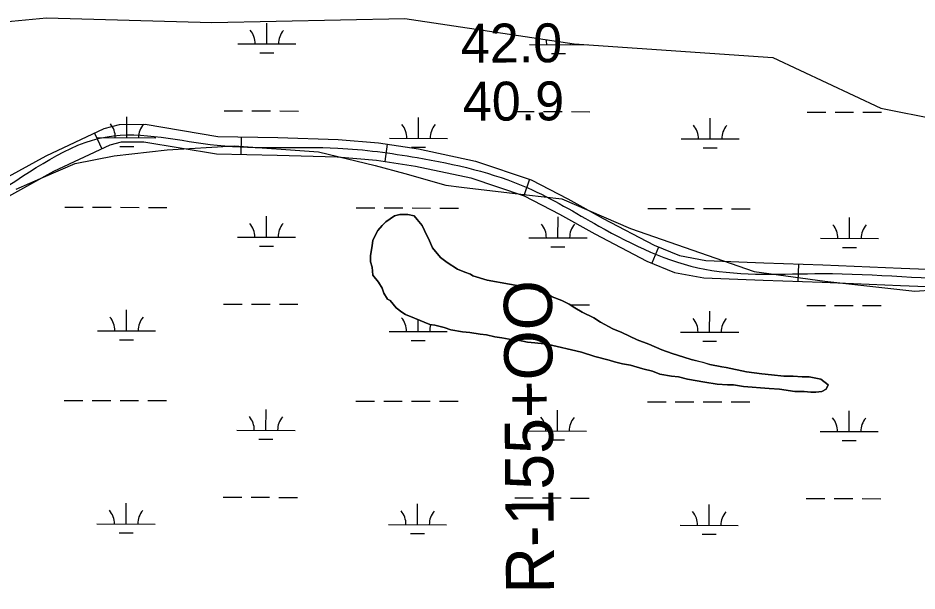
# Model space of a CAD drawing. Extents: x 3180038 to 3217926, y 922069 to 947485.
# Drawn here: x 3184913 to 3186460, y 931017 to 932004 of the extents above; entities that cross this region are included whole.
import ezdxf

# ---------------------------------------------------------------- set-up
doc = ezdxf.new("R2010")
doc.units = 0
for name, color, linetype in [('V-RIVR-RANG', 7, 'Continuous'), ('V-RIVR-RANG-IDEN', 7, 'Continuous'), ('V-ROAD-CNTR', 7, 'Continuous'), ('V-SITE-VEGE', 7, 'Continuous'), ('V-TOPO-SHOR', 7, 'Continuous'), ('V-WETL-SWMP', 7, 'Continuous')]:
    doc.layers.add(name, color=color, linetype=linetype)

msp = doc.modelspace()

# ---------------------------------------------------------------- linework, layer by layer
at = {"layer": 'V-ROAD-CNTR'}
for p, q in [((3185044.5, 931805.8), (3185057.3, 931778.7)), ((3185297.1, 931799.1), (3185296.5, 931769.1)), ((3185548.5, 931786.4), (3185544.1, 931756.8)), ((3185793.3, 931726.3), (3185783.7, 931697.9)), ((3186015.3, 931609.5), (3186003.9, 931581.8)), ((3186256.2, 931580.3), (3186255.1, 931550.3))]:
    msp.add_line(p, q, dxfattribs=at)
for points in [[(3184866.8, 931714.7), (3184961.2, 931766.7), (3185061.1, 931813.6), (3185087.4, 931820.4), (3185131.6, 931821), (3185257.2, 931799.9), (3185360, 931797.9), (3185464.3, 931794.9), (3185533.6, 931788.7), (3185602.6, 931778.4), (3185700.5, 931757.6), (3185796.2, 931725.3), (3185859.2, 931692.5), (3185920.1, 931658.7), (3186008, 931612.5), (3186051.6, 931594.7), (3186096.7, 931586.3), (3186196.9, 931582.4), (3186298.2, 931578.8), (3186433.1, 931573.4), (3186567.7, 931568)], [(3184881.1, 931688.3), (3184974.8, 931740), (3185071.3, 931785.3), (3185091.3, 931790.4), (3185129.3, 931790.9), (3185254.4, 931770), (3185359.3, 931767.9), (3185462.5, 931764.9), (3185530, 931758.9), (3185597.3, 931748.9), (3185692.6, 931728.7), (3185784.4, 931697.6), (3185845, 931666.1), (3185905.9, 931632.3), (3185995.4, 931585.3), (3186043.1, 931565.8), (3186093.3, 931556.4), (3186195.8, 931552.4), (3186297.1, 931548.9), (3186431.9, 931543.4), (3186567.2, 931538)]]:
    msp.add_lwpolyline(points, dxfattribs=at)
msp.add_spline([(3184272.5, 931571.5), (3184273.3, 931572), (3184388.9, 931608.9), (3184482.3, 931629.3), (3184594.3, 931629), (3184801.1, 931663.1), (3184874, 931701.5), (3185066.2, 931799.5), (3185255.8, 931784.9), (3185463.4, 931779.9), (3185599.9, 931763.6), (3185790.3, 931711.5), (3185913, 931645.5), (3186095, 931571.4), (3186297.6, 931563.8), (3186567.5, 931553), (3186727.4, 931556.9), (3186879, 931529.3), (3186914.3, 931400.2), (3186887.7, 931205.9), (3186857.5, 930948.7), (3186884.4, 930867.9), (3186934.5, 930827.1), (3186969.1, 930750.7), (3186952, 930670.5)], degree=3, dxfattribs=at)
at = {"layer": 'V-SITE-VEGE'}
for p, q in [((3185546.1, 931653.1), (3185561.2, 931663.1)), ((3185561.2, 931663.1), (3185570, 931665.6)), ((3185570, 931665.6), (3185583.8, 931665.7)), ((3185583.8, 931665.7), (3185595.1, 931663.1)), ((3185595.1, 931663.1), (3185600.1, 931656.9)), ((3185539.8, 931646.8), (3185546.1, 931653.1)), ((3185600.1, 931656.9), (3185608.9, 931646.8)), ((3185523.5, 931621.6), (3185532.3, 931638)), ((3185532.3, 931638), (3185539.8, 931646.8)), ((3185608.9, 931646.8), (3185612.7, 931638)), ((3185612.7, 931638), (3185621.5, 931620.4)), ((3185522.3, 931611.6), (3185523.5, 931621.6)), ((3185621.5, 931620.4), (3185626.5, 931607.9)), ((3185519.8, 931595.2), (3185522.3, 931611.6)), ((3185626.5, 931607.9), (3185640.4, 931591.6)), ((3185519.8, 931583.9), (3185519.8, 931595.2)), ((3185640.4, 931591.6), (3185651.7, 931582.8)), ((3185522.3, 931575.1), (3185519.8, 931583.9)), ((3185523.5, 931561.3), (3185522.3, 931575.1)), ((3185651.7, 931582.8), (3185669.3, 931571.5)), ((3185669.3, 931571.5), (3185681.9, 931566.5)), ((3185533.6, 931548.8), (3185523.5, 931561.3)), ((3185681.9, 931566.5), (3185691.9, 931562.7)), ((3185691.9, 931562.7), (3185695.7, 931560.2)), ((3185695.7, 931560.2), (3185720.8, 931552.7)), ((3185539.9, 931538.7), (3185533.6, 931548.8)), ((3185542.4, 931529.9), (3185539.9, 931538.7)), ((3185720.8, 931552.7), (3185797.5, 931538.9)), ((3185797.5, 931538.9), (3185806.3, 931536.4)), ((3185548.7, 931519.9), (3185542.4, 931529.9)), ((3185806.3, 931536.4), (3185812.6, 931532.6)), ((3185812.6, 931532.6), (3185822.6, 931530.1)), ((3185822.6, 931530.1), (3185832.7, 931523.8)), ((3185832.7, 931523.8), (3185849, 931517.6)), ((3185553.7, 931517.4), (3185548.7, 931519.9)), ((3185563.8, 931504.8), (3185553.7, 931517.4)), ((3185849, 931517.6), (3185861.6, 931511.3)), ((3185861.6, 931511.3), (3185871.6, 931505)), ((3185573.9, 931497.3), (3185563.8, 931504.8)), ((3185580.1, 931493.5), (3185573.9, 931497.3)), ((3185595.2, 931487.2), (3185580.1, 931493.5)), ((3185871.6, 931505), (3185884.2, 931497.5)), ((3185884.2, 931497.5), (3185904.3, 931487.5)), ((3185621.6, 931476), (3185595.2, 931487.2)), ((3185904.3, 931487.5), (3185915.6, 931479.9)), ((3185915.6, 931479.9), (3185937, 931468.6)), ((3185630.4, 931474.7), (3185621.6, 931476)), ((3185646.7, 931470.9), (3185630.4, 931474.7)), ((3185658.1, 931467.2), (3185646.7, 931470.9)), ((3185678.2, 931463.4), (3185658.1, 931467.2)), ((3185690.7, 931462.2), (3185678.2, 931463.4)), ((3185708.3, 931459.7), (3185690.7, 931462.2)), ((3185937, 931468.6), (3185952.1, 931462.4)), ((3185952.1, 931462.4), (3185978.5, 931449.8)), ((3185719.6, 931458.4), (3185708.3, 931459.7)), ((3185733.5, 931454.7), (3185719.6, 931458.4)), ((3185746, 931453.4), (3185733.5, 931454.7)), ((3185758.6, 931450.9), (3185746, 931453.4)), ((3185771.2, 931449.7), (3185758.6, 931450.9)), ((3185790, 931445.9), (3185771.2, 931449.7)), ((3185802.6, 931444.7), (3185790, 931445.9)), ((3185978.5, 931449.8), (3185998.6, 931442.3)), ((3185823.9, 931442.2), (3185802.6, 931444.7)), ((3185883, 931428.4), (3185823.9, 931442.2)), ((3185998.6, 931442.3), (3186021.2, 931432.3)), ((3186021.2, 931432.3), (3186038.8, 931426)), ((3185905.6, 931420.9), (3185883, 931428.4)), ((3185930.7, 931414.6), (3185905.6, 931420.9)), ((3186038.8, 931426), (3186058.9, 931419.7)), ((3186058.9, 931419.7), (3186071.5, 931416)), ((3186071.5, 931416), (3186091.6, 931411)), ((3185939.5, 931412.1), (3185930.7, 931414.6)), ((3185953.4, 931408.3), (3185939.5, 931412.1)), ((3185967.2, 931405.8), (3185953.4, 931408.3)), ((3185988.6, 931399.6), (3185967.2, 931405.8)), ((3186004.9, 931395.8), (3185988.6, 931399.6)), ((3186091.6, 931411), (3186104.1, 931407.2)), ((3186104.1, 931407.2), (3186124.2, 931403.4)), ((3186124.2, 931403.4), (3186131.8, 931402.2)), ((3186131.8, 931402.2), (3186167, 931394.7)), ((3186017.5, 931390.8), (3186004.9, 931395.8)), ((3186037.6, 931387), (3186017.5, 931390.8)), ((3186050.1, 931385.8), (3186037.6, 931387)), ((3186065.2, 931382), (3186050.1, 931385.8)), ((3186167, 931394.7), (3186193.4, 931390.9)), ((3186193.4, 931390.9), (3186209.7, 931389.7)), ((3186209.7, 931389.7), (3186231.1, 931387.2)), ((3186231.1, 931387.2), (3186247.4, 931387.2)), ((3186247.4, 931387.2), (3186262.5, 931385.9)), ((3186262.5, 931385.9), (3186275, 931386)), ((3186275, 931386), (3186295.1, 931382.2)), ((3186095.4, 931377), (3186065.2, 931382)), ((3186116.7, 931373.3), (3186095.4, 931377)), ((3186134.3, 931372), (3186116.7, 931373.3)), ((3186144.4, 931372), (3186134.3, 931372)), ((3186162, 931369.5), (3186144.4, 931372)), ((3186205.9, 931365.8), (3186162, 931369.5)), ((3186295.1, 931382.2), (3186307.7, 931372.2)), ((3186307.7, 931372.2), (3186304, 931364.6)), ((3186223.5, 931364.6), (3186205.9, 931365.8)), ((3186249.9, 931360.8), (3186223.5, 931364.6)), ((3186266.3, 931360.8), (3186249.9, 931360.8)), ((3186277.6, 931359.6), (3186266.3, 931360.8)), ((3186286.4, 931359.6), (3186277.6, 931359.6)), ((3186296.4, 931360.8), (3186286.4, 931359.6)), ((3186304, 931364.6), (3186296.4, 931360.8))]:
    msp.add_line(p, q, dxfattribs=at)
at = {"layer": 'V-TOPO-SHOR'}
msp.add_lwpolyline([(3184909.8, 931709.3), (3184957.1, 931729.6), (3185011.2, 931753.2), (3185078.7, 931766.7), (3185169.9, 931776.9), (3185284.8, 931783.6), (3185430, 931773.5), (3185528, 931749.8), (3185578.7, 931736.3), (3185649.6, 931716.1), (3185676.6, 931712.7), (3185788.1, 931699.2), (3185848.9, 931692.4), (3185967.1, 931641.7), (3186179.9, 931567.4), (3186301.6, 931550.5), (3186456.9, 931533.6), (3186554.9, 931540.4)], dxfattribs=at)
at = {"layer": 'V-WETL-SWMP'}
for p, q in [((3184691, 931979.1), (3184961.8, 932004)), ((3184961.8, 932004), (3185246.5, 931996.2)), ((3185246.5, 931996.2), (3185579, 932003)), ((3185579, 932003), (3185870.2, 931959.6)), ((3185341.3, 931959.3), (3185341.4, 931995.3)), ((3185291.3, 931959.4), (3185391.3, 931959.2)), ((3185793.2, 931958.3), (3185892.8, 931958)), ((3185843.2, 931958.1), (3185843.2, 931963.6)), ((3185870.2, 931959.6), (3186212.2, 931935.9)), ((3185329.2, 931943.9), (3185353.2, 931943.8)), ((3185831.1, 931942.7), (3185855.1, 931942.7)), ((3186212.2, 931935.9), (3186398.1, 931848.9)), ((3186398.1, 931848.9), (3186672.6, 931793.9)), ((3185100.4, 931798), (3185100.5, 931834)), ((3185267.6, 931844), (3185299.6, 931843.9)), ((3185315.6, 931843.9), (3185347.6, 931843.8)), ((3185363.6, 931843.8), (3185395.6, 931843.7)), ((3185602.3, 931796.8), (3185602.4, 931832.8)), ((3185769.5, 931842.9), (3185801.5, 931842.8)), ((3185817.5, 931842.8), (3185849.5, 931842.7)), ((3185865.5, 931842.7), (3185897.5, 931842.6)), ((3186271.4, 931841.7), (3186303.4, 931841.7)), ((3186319.4, 931841.6), (3186351.4, 931841.6)), ((3186367.4, 931841.5), (3186399.4, 931841.5)), ((3186104.3, 931795.7), (3186104.3, 931831.7)), ((3185050.4, 931798.1), (3185150.4, 931797.8)), ((3185552.3, 931796.9), (3185652.3, 931796.7)), ((3186054.3, 931795.8), (3186154.3, 931795.6)), ((3185088.4, 931782.6), (3185112.4, 931782.5)), ((3185590.3, 931781.4), (3185614.3, 931781.4)), ((3186092.2, 931780.3), (3186116.2, 931780.2)), ((3184993.3, 931678.1), (3185025.3, 931678.1)), ((3185041.3, 931678), (3185073.3, 931677.9)), ((3185089.3, 931677.9), (3185121.3, 931677.8)), ((3185137.3, 931677.8), (3185169.3, 931677.7)), ((3185340.5, 931626.6), (3185340.6, 931662.6)), ((3185495.2, 931677), (3185527.2, 931676.9)), ((3185543.2, 931676.9), (3185575.2, 931676.8)), ((3185561.2, 931663.1), (3185546.1, 931653.1)), ((3185570, 931665.6), (3185561.2, 931663.1)), ((3185583.8, 931665.6), (3185570, 931665.6)), ((3185595.1, 931663.1), (3185583.8, 931665.6)), ((3185591.2, 931676.8), (3185623.2, 931676.7)), ((3185600.1, 931656.9), (3185595.1, 931663.1)), ((3185639.2, 931676.7), (3185671.2, 931676.6)), ((3185997.1, 931675.9), (3186029.1, 931675.8)), ((3186045.1, 931675.8), (3186077.1, 931675.7)), ((3186093.1, 931675.6), (3186125.1, 931675.6)), ((3186141.1, 931675.5), (3186173.1, 931675.5)), ((3185546.1, 931653.1), (3185539.8, 931646.8)), ((3185608.9, 931646.8), (3185600.1, 931656.9)), ((3185842.4, 931625.5), (3185842.5, 931661.5)), ((3186344.3, 931624.3), (3186344.4, 931660.3)), ((3185532.3, 931638), (3185523.5, 931621.6)), ((3185539.8, 931646.8), (3185532.3, 931638)), ((3185612.7, 931638), (3185608.9, 931646.8)), ((3185621.5, 931620.4), (3185612.7, 931638)), ((3185290.5, 931626.7), (3185390.5, 931626.5)), ((3185523.5, 931621.6), (3185522.3, 931611.6)), ((3185626.5, 931607.9), (3185621.5, 931620.4)), ((3185792.4, 931625.6), (3185892.4, 931625.4)), ((3186294.3, 931624.5), (3186394.3, 931624.2)), ((3185328.5, 931611.2), (3185352.5, 931611.1)), ((3185522.3, 931611.6), (3185519.8, 931595.2)), ((3185640.4, 931591.6), (3185626.5, 931607.9)), ((3185830.4, 931610.1), (3185854.4, 931610)), ((3186332.3, 931608.9), (3186356.3, 931608.9)), ((3185519.8, 931595.2), (3185519.8, 931583.9)), ((3185651.7, 931582.8), (3185640.4, 931591.6)), ((3185519.8, 931583.9), (3185522.3, 931575.1)), ((3185522.3, 931575.1), (3185523.6, 931561.3)), ((3185669.3, 931571.5), (3185651.7, 931582.8)), ((3185681.9, 931566.5), (3185669.3, 931571.5)), ((3185523.6, 931561.3), (3185533.6, 931548.8)), ((3185691.9, 931562.7), (3185681.9, 931566.5)), ((3185695.7, 931560.2), (3185691.9, 931562.7)), ((3185720.8, 931552.7), (3185695.7, 931560.2)), ((3185533.6, 931548.8), (3185539.9, 931538.7)), ((3185539.9, 931538.7), (3185542.4, 931529.9)), ((3185797.5, 931538.9), (3185720.8, 931552.7)), ((3185806.3, 931536.4), (3185797.5, 931538.9)), ((3185542.4, 931529.9), (3185548.7, 931519.9)), ((3185812.6, 931532.6), (3185806.3, 931536.4)), ((3185822.6, 931530.1), (3185812.6, 931532.6)), ((3185832.7, 931523.8), (3185822.6, 931530.1)), ((3185849, 931517.6), (3185832.7, 931523.8)), ((3185266.9, 931511.3), (3185298.9, 931511.3)), ((3185314.9, 931511.2), (3185346.9, 931511.2)), ((3185362.9, 931511.1), (3185394.9, 931511)), ((3185548.7, 931519.9), (3185553.7, 931517.4)), ((3185553.7, 931517.4), (3185563.8, 931504.8)), ((3185861.6, 931511.3), (3185849, 931517.6)), ((3185871.6, 931505), (3185861.6, 931511.3)), ((3185864.8, 931510), (3185896.8, 931509.9)), ((3186270.7, 931509.1), (3186302.7, 931509)), ((3186318.7, 931509), (3186350.7, 931508.9)), ((3186366.7, 931508.9), (3186398.7, 931508.8)), ((3185099.7, 931465.3), (3185099.8, 931501.3)), ((3185563.8, 931504.8), (3185573.9, 931497.3)), ((3185573.9, 931497.3), (3185580.1, 931493.5)), ((3185580.1, 931493.5), (3185595.2, 931487.2)), ((3185884.2, 931497.5), (3185871.6, 931505)), ((3185904.3, 931487.5), (3185884.2, 931497.5)), ((3186103.5, 931463), (3186103.6, 931499)), ((3185595.2, 931487.2), (3185621.6, 931475.9)), ((3185601.6, 931464.2), (3185601.6, 931484.5)), ((3185915.6, 931479.9), (3185904.3, 931487.5)), ((3185937, 931468.6), (3185915.6, 931479.9)), ((3185049.7, 931465.4), (3185149.7, 931465.2)), ((3185551.6, 931464.3), (3185651.6, 931464)), ((3185621.6, 931475.9), (3185630.4, 931474.7)), ((3185630.4, 931474.7), (3185646.7, 931470.9)), ((3185646.7, 931470.9), (3185658.1, 931467.2)), ((3185658.1, 931467.2), (3185678.2, 931463.4)), ((3185678.2, 931463.4), (3185690.7, 931462.2)), ((3185690.7, 931462.2), (3185708.3, 931459.7)), ((3185952.1, 931462.4), (3185937, 931468.6)), ((3185978.5, 931449.8), (3185952.1, 931462.4)), ((3186053.5, 931463.1), (3186153.5, 931462.9)), ((3185087.7, 931449.9), (3185111.7, 931449.8)), ((3185589.6, 931448.7), (3185613.6, 931448.7)), ((3185708.3, 931459.7), (3185719.6, 931458.4)), ((3185719.6, 931458.4), (3185733.5, 931454.7)), ((3185733.5, 931454.7), (3185746, 931453.4)), ((3185746, 931453.4), (3185758.6, 931450.9)), ((3185758.6, 931450.9), (3185771.2, 931449.7)), ((3185771.2, 931449.7), (3185790, 931445.9)), ((3185790, 931445.9), (3185802.6, 931444.7)), ((3185998.6, 931442.3), (3185978.5, 931449.8)), ((3186091.5, 931447.6), (3186115.5, 931447.6)), ((3185802.6, 931444.7), (3185823.9, 931442.2)), ((3185823.9, 931442.2), (3185883, 931428.4)), ((3186021.2, 931432.3), (3185998.6, 931442.3)), ((3186038.8, 931426), (3186021.2, 931432.3)), ((3185883, 931428.4), (3185905.6, 931420.9)), ((3185905.6, 931420.9), (3185930.7, 931414.6)), ((3186058.9, 931419.7), (3186038.8, 931426)), ((3186071.5, 931416), (3186058.9, 931419.7)), ((3186091.6, 931410.9), (3186071.5, 931416)), ((3185930.7, 931414.6), (3185939.5, 931412.1)), ((3185939.5, 931412.1), (3185953.4, 931408.3)), ((3185953.4, 931408.3), (3185967.2, 931405.8)), ((3185967.2, 931405.8), (3185988.6, 931399.6)), ((3185988.6, 931399.6), (3186004.9, 931395.8)), ((3186104.1, 931407.2), (3186091.6, 931410.9)), ((3186124.3, 931403.4), (3186104.1, 931407.2)), ((3186131.8, 931402.2), (3186124.3, 931403.4)), ((3186167, 931394.7), (3186131.8, 931402.2)), ((3186004.9, 931395.8), (3186017.5, 931390.8)), ((3186017.5, 931390.8), (3186037.6, 931387)), ((3186037.6, 931387), (3186050.1, 931385.8)), ((3186050.1, 931385.8), (3186065.2, 931382)), ((3186193.4, 931390.9), (3186167, 931394.7)), ((3186209.7, 931389.7), (3186193.4, 931390.9)), ((3186231.1, 931387.2), (3186209.7, 931389.7)), ((3186247.4, 931387.2), (3186231.1, 931387.2)), ((3186262.5, 931385.9), (3186247.4, 931387.2)), ((3186275, 931385.9), (3186262.5, 931385.9)), ((3186295.1, 931382.2), (3186275, 931385.9)), ((3186065.2, 931382), (3186095.4, 931377)), ((3186095.4, 931377), (3186116.7, 931373.3)), ((3186116.7, 931373.3), (3186134.3, 931372)), ((3186134.3, 931372), (3186144.4, 931372)), ((3186144.4, 931372), (3186162, 931369.5)), ((3186162, 931369.5), (3186205.9, 931365.8)), ((3186307.7, 931372.1), (3186295.1, 931382.2)), ((3186304, 931364.6), (3186307.7, 931372.1)), ((3186205.9, 931365.8), (3186223.5, 931364.5)), ((3186223.5, 931364.5), (3186249.9, 931360.8)), ((3186249.9, 931360.8), (3186266.3, 931360.8)), ((3186266.3, 931360.8), (3186277.6, 931359.6)), ((3186277.6, 931359.6), (3186286.4, 931359.6)), ((3186286.4, 931359.6), (3186296.4, 931360.8)), ((3186296.4, 931360.8), (3186304, 931364.6)), ((3184992.6, 931345.5), (3185024.6, 931345.4)), ((3185040.6, 931345.3), (3185072.6, 931345.3)), ((3185088.6, 931345.2), (3185120.6, 931345.2)), ((3185136.6, 931345.1), (3185168.6, 931345.1)), ((3185494.5, 931344.3), (3185526.5, 931344.3)), ((3185542.5, 931344.2), (3185574.5, 931344.1)), ((3185590.5, 931344.1), (3185622.5, 931344)), ((3185638.5, 931344), (3185670.5, 931343.9)), ((3185996.4, 931343.2), (3186028.4, 931343.1)), ((3186044.4, 931343.1), (3186076.4, 931343)), ((3186092.4, 931343), (3186124.4, 931342.9)), ((3186140.4, 931342.9), (3186172.4, 931342.8)), ((3185339.8, 931293.9), (3185339.9, 931329.9)), ((3185841.7, 931292.8), (3185841.8, 931328.8)), ((3186343.6, 931291.7), (3186343.7, 931327.7)), ((3185289.8, 931294), (3185389.8, 931293.8)), ((3185791.7, 931292.9), (3185891.7, 931292.7)), ((3186293.6, 931291.8), (3186393.6, 931291.6)), ((3185327.7, 931278.5), (3185351.7, 931278.5)), ((3185829.6, 931277.4), (3185853.6, 931277.3)), ((3186331.6, 931276.3), (3186355.6, 931276.2)), ((3185098.9, 931132.6), (3185099, 931168.6)), ((3185266.1, 931178.7), (3185298.1, 931178.6)), ((3185314.1, 931178.6), (3185346.1, 931178.5)), ((3185362.1, 931178.4), (3185394.1, 931178.4)), ((3185600.8, 931131.5), (3185600.9, 931167.5)), ((3185768, 931177.5), (3185800, 931177.5)), ((3185816, 931177.4), (3185848, 931177.4)), ((3185864, 931177.3), (3185896, 931177.2)), ((3186269.9, 931176.4), (3186301.9, 931176.3)), ((3186317.9, 931176.3), (3186349.9, 931176.2)), ((3186365.9, 931176.2), (3186397.9, 931176.1)), ((3186102.8, 931130.3), (3186102.8, 931166.3)), ((3185048.9, 931132.7), (3185148.9, 931132.5)), ((3185550.8, 931131.6), (3185650.8, 931131.4)), ((3186052.8, 931130.5), (3186152.8, 931130.2)), ((3185086.9, 931117.2), (3185110.9, 931117.2)), ((3185588.8, 931116.1), (3185612.8, 931116)), ((3186090.7, 931114.9), (3186114.7, 931114.9))]:
    msp.add_line(p, q, dxfattribs=at)
for centre, start, end in [((3185286, 931959.9), 359.099, 40.6427), ((3185396.5, 931959.6), 139.099, 180.6427), ((3185787.9, 931958.7), 359.099, 13.103), ((3185898.4, 931958.5), 176.5219, 180.6427), ((3185045.2, 931798.6), 359.099, 40.6427), ((3185155.7, 931798.3), 139.099, 180.6427), ((3185547.1, 931797.4), 359.099, 40.6427), ((3185657.6, 931797.2), 139.099, 180.6427), ((3186049, 931796.3), 359.099, 40.6427), ((3186159.5, 931796), 139.099, 180.6427), ((3185285.3, 931627.2), 359.099, 40.6427), ((3185395.8, 931627), 139.099, 180.6427), ((3185787.2, 931626.1), 359.099, 40.6427), ((3185897.7, 931625.8), 139.099, 180.6427), ((3186289.1, 931624.9), 359.099, 40.6427), ((3186399.6, 931624.7), 139.099, 180.6427), ((3185044.4, 931465.9), 359.099, 40.6427), ((3185154.9, 931465.6), 139.099, 180.6427), ((3185546.4, 931464.8), 359.099, 40.6427), ((3186048.3, 931463.6), 359.099, 40.6427), ((3186158.7, 931463.4), 139.099, 180.6427), ((3185656.8, 931464.5), 161.4982, 180.6427), ((3185284.5, 931294.5), 359.099, 40.6427), ((3185395, 931294.3), 139.099, 180.6427), ((3185786.4, 931293.4), 359.099, 40.6427), ((3185896.9, 931293.1), 139.099, 180.6427), ((3186288.3, 931292.3), 359.099, 40.6427), ((3186398.8, 931292), 139.099, 180.6427), ((3185043.7, 931133.2), 359.099, 40.6427), ((3185154.2, 931133), 139.099, 180.6427), ((3185545.6, 931132.1), 359.099, 40.6427), ((3185656.1, 931131.8), 139.099, 180.6427), ((3186047.5, 931130.9), 359.099, 40.6427), ((3186158, 931130.7), 139.099, 180.6427)]:
    msp.add_arc(centre, 35.2, start, end, dxfattribs=at)

# ---------------------------------------------------------------- texts
at = {"layer": 'V-RIVR-RANG'}
for s, p in [('42.0', (3185675.4, 931926.9)), ('40.9', (3185678.8, 931826.9))]:
    msp.add_text(s, height=67, rotation=0.2883, dxfattribs=at).set_placement(p)
at = {"layer": 'V-RIVR-RANG-IDEN'}
msp.add_text('R-155+OO', height=83, rotation=90.4316, dxfattribs=at).set_placement((3185835.9, 931013))

doc.saveas('drawing.dxf')
